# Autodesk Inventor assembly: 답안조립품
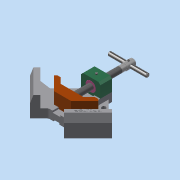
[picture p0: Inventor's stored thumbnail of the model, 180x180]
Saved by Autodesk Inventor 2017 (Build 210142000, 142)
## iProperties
Part Number: 답안조립품
Material: 일반
Document SubType Name: Assembly
Designer: mrc
Author: mrc
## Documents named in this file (11)
- C:\Users\mrc\Desktop\700506V1036\답안조립품.iam
- C:\Users\mrc\Desktop\700506V1036\본체.ipt
- C:\Users\mrc\Desktop\700506V1036\리드스크류.ipt
- C:\Users\mrc\Desktop\700506V1036\멈춤나사 M4x5.ipt
- C:\Users\mrc\Desktop\700506V1036\멈춤나사 M4x10.ipt
- C:\Users\mrc\Desktop\700506V1036\볼트 M4x16.ipt
- C:\Users\mrc\Desktop\700506V1036\부시.ipt
- C:\Users\mrc\Desktop\700506V1036\서포트.ipt
- C:\Users\mrc\Desktop\700506V1036\조.ipt
- C:\Users\mrc\Desktop\700506V1036\평행 핀 2.5x24.ipt
- C:\Users\mrc\Desktop\700506V1036\핸들.ipt
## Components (1 placed, 1 different names)
1. 핸들:1
